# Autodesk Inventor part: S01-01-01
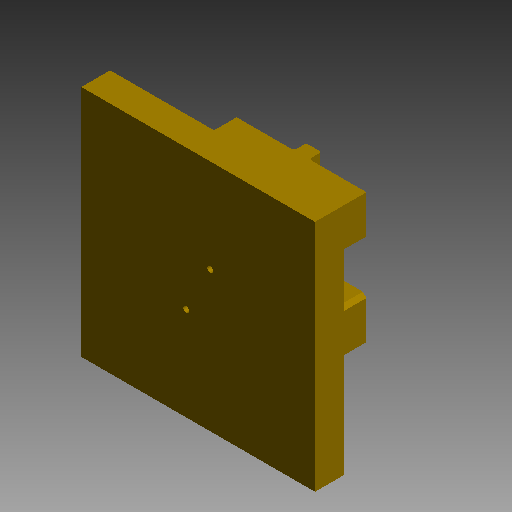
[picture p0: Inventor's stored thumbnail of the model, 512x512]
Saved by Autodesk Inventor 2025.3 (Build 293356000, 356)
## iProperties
Part Number: S01-01-01
Material: Generický
Document SubType Name: Modelování
Designer: Patrik
Density: 1 g/cm^3
Appearance: Zlatá
Description: Tvárnice
Mass: 65.8472 g
Surface Area: 141.16 cm^2
Volume: 65.8472 cm^3
Author: Patrik
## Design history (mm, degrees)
node "Sestava - mold design_MODEL - mk4 Blenddoor Tab v4_2_CV_Base"
node "Pracovní rovina1"
feature "Vyřezání2"
node "Objemová tělesa"
node "Povrchová tělesa"
feature "Těleso8::Sestava - mold design_MODEL - mk4 Blenddoor Tab v4_"
tag "Prvek štítků3"
node "Těleso8"
feature "Sestava - mold design_MODEL - mk4 Blenddoor Tab v4_2_CV_Base"
feature "Plocha4"
node "Povrch4"
